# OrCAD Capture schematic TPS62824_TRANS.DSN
size D; title: TPS62824 2.4-V to 5.5-V input 1-A Step-Down Converter with; rev: 1.0; note: Datasheet: SLVSEF9F                      EVM: SLVUBE4; note: Synchronous Step Down Converter
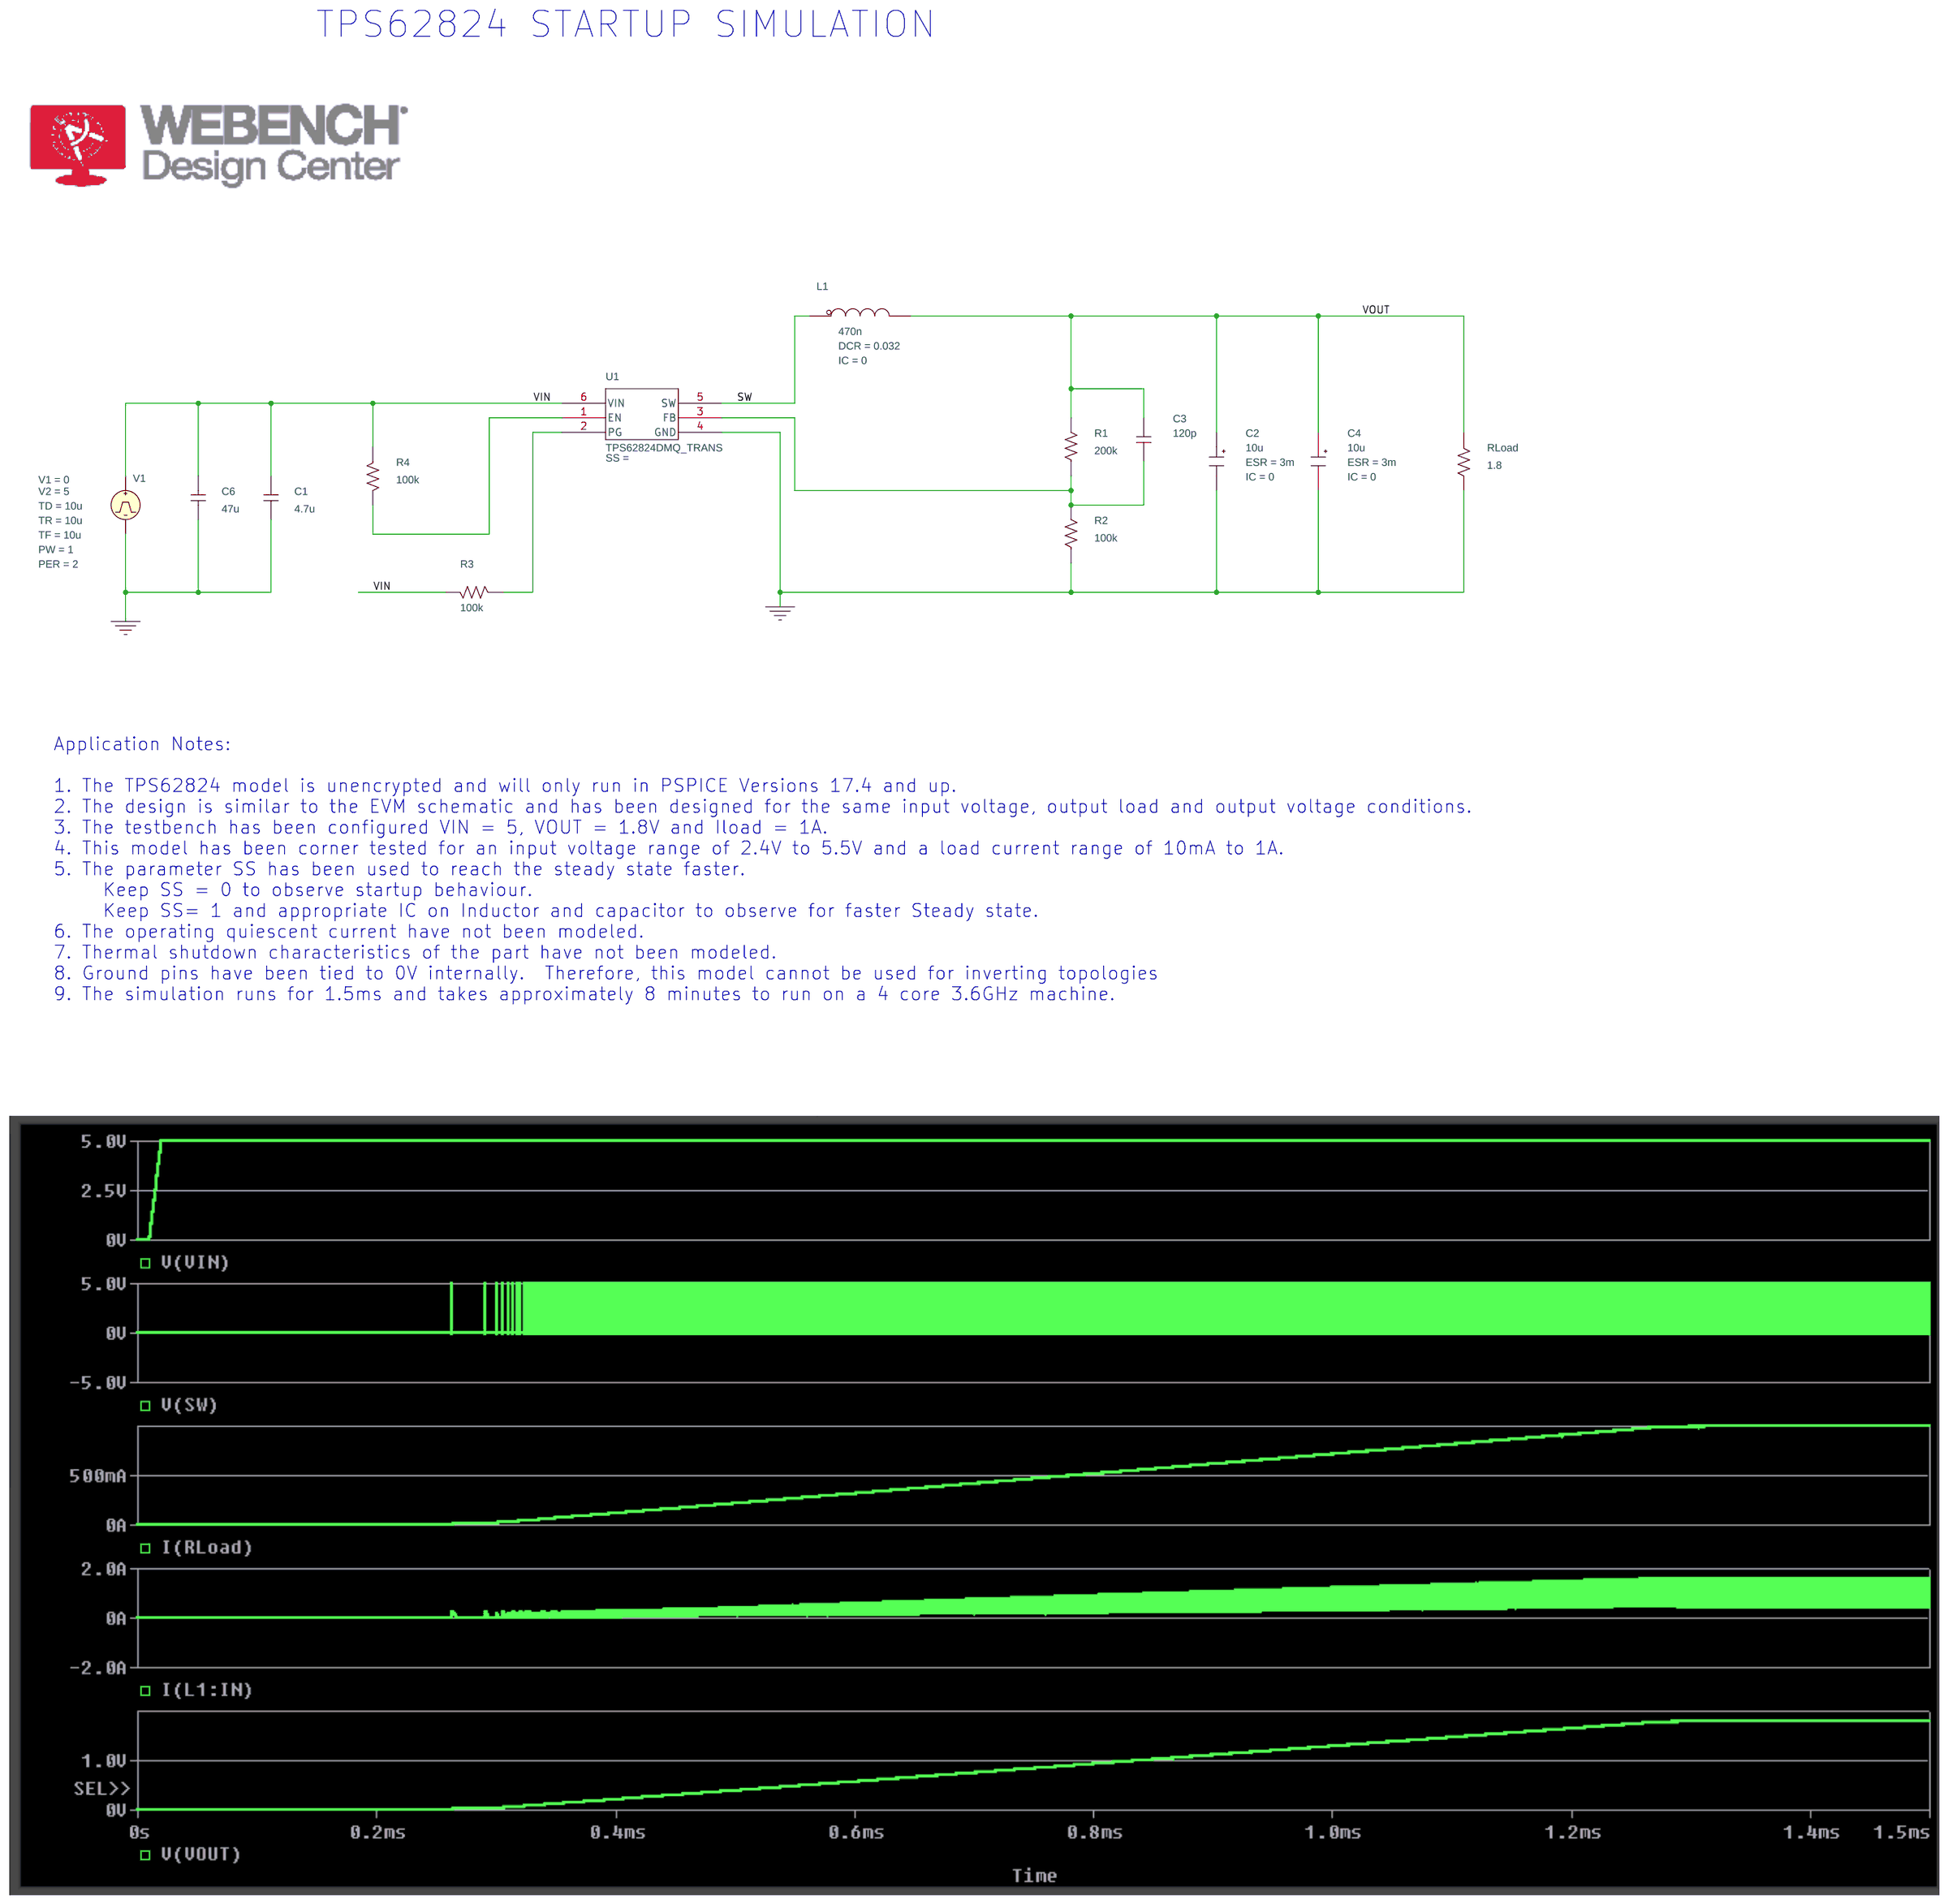
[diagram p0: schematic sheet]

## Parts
C1  4.7u  [RAD/CK05]
C2  CESR
C3  120p  [RAD/CK05]
C4  CESR
C6  47u  [RAD/CK05]
L1  LDCR
R1  200k  [AX/RC05]
R2  100k  [AX/RC05]
R3  100k  [AX/RC05]
R4  100k  [AX/RC05]
RLoad  1.8  [AX/RC05]
U1  TPS62824DMQ_TRANS  [DMQ0006A-MFG]
V1  VPULSE

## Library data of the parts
C1 C6 = C: IC: 0
C2 C4 = CESR_0: C: 10u; ESR: 3m; IC: 0; PSpiceTemplate: X^@REFDES %IN %OUT @MODEL PARAMS:  ?C|C=@C||C=100u|  ?ESR|ESR=@ESR||ESR=0.01| ?X|X=@X||X=2|  ?IC|IC=@IC||IC=2|; X: 1
C3 = C
L1 = LDCR_0: DCR: 0.032; IC: 0; L: 470n; PSpiceTemplate: X^@REFDES %IN %OUT @MODEL PARAMS:  ?L|L=@L||L=1u|  ?DCR|DCR=@DCR||DCR=0.01| ?IC|IC=@IC||IC=0|
R1-R4 RLoad = R
U1 = TPS62824DMQ_TRANS
V1 = VPULSE: PER: 2; PW: 1; TD: 10u; TF: 10u; TR: 10u; V1: 0; V2: 5

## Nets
VIN: C1.1 C6.1 R3.2 R4.1 U1.6(VIN) V1.1(+)
0: C1.2 C2.3(OUT) C4.3(OUT) C6.2 R2.1 RLoad.2 U1.4(GND) V1.2(-)
SW: L1.1(IN) U1.5(SW)
VOUT: C2.1(IN) C3.1 C4.1(IN) L1.3(OUT) R1.2 RLoad.1
N16780303: R4.2 U1.1(EN)
N16780308: C3.2 R1.1 R2.2 U1.3(FB)
N16780379: R3.1 U1.2(PG)

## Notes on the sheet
- TPS62824 STARTUP SIMULATION
- Application Notes:
  1. The TPS62824 model is unencrypted and will only run in PSPICE Versions 17.4 and up.
  2. The design is similar to the EVM schematic and has been designed for the same input voltage, output load and output voltage conditions.
  3. The testbench has been configured VIN = 5, VOUT = 1.8V and Iload = 1A.
  4. This model has been corner tested for an input voltage range of 2.4V to 5.5V and a load current range of 10mA to 1A.
  5. The parameter SS has been used to reach the steady state faster.
       Keep SS = 0 to observe startup behaviour.
       Keep SS= 1 and appropriate IC on Inductor and capacitor to observe for faster Steady state.
  6. The operating quiescent current have not been modeled.
  7. Thermal shutdown characteristics of the part have not been modeled.
  8. Ground pins have been tied to 0V internally.  Therefore, this model cannot be used for inverting topologies
  9. The simulation runs for 1.5ms and takes approximately 8 minutes to run on a 4 core 3.6GHz machine.
